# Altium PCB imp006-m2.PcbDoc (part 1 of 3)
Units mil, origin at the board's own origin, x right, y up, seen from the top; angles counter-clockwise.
Board outline 1181.1 x 1515.75 mil, 4 copper layers (Top Layer, Signal Layer 1, Signal Layer 2, Bottom Layer), stack 31.759 mil thick; 78 components, 116 nets, 508 pads, 482 vias.
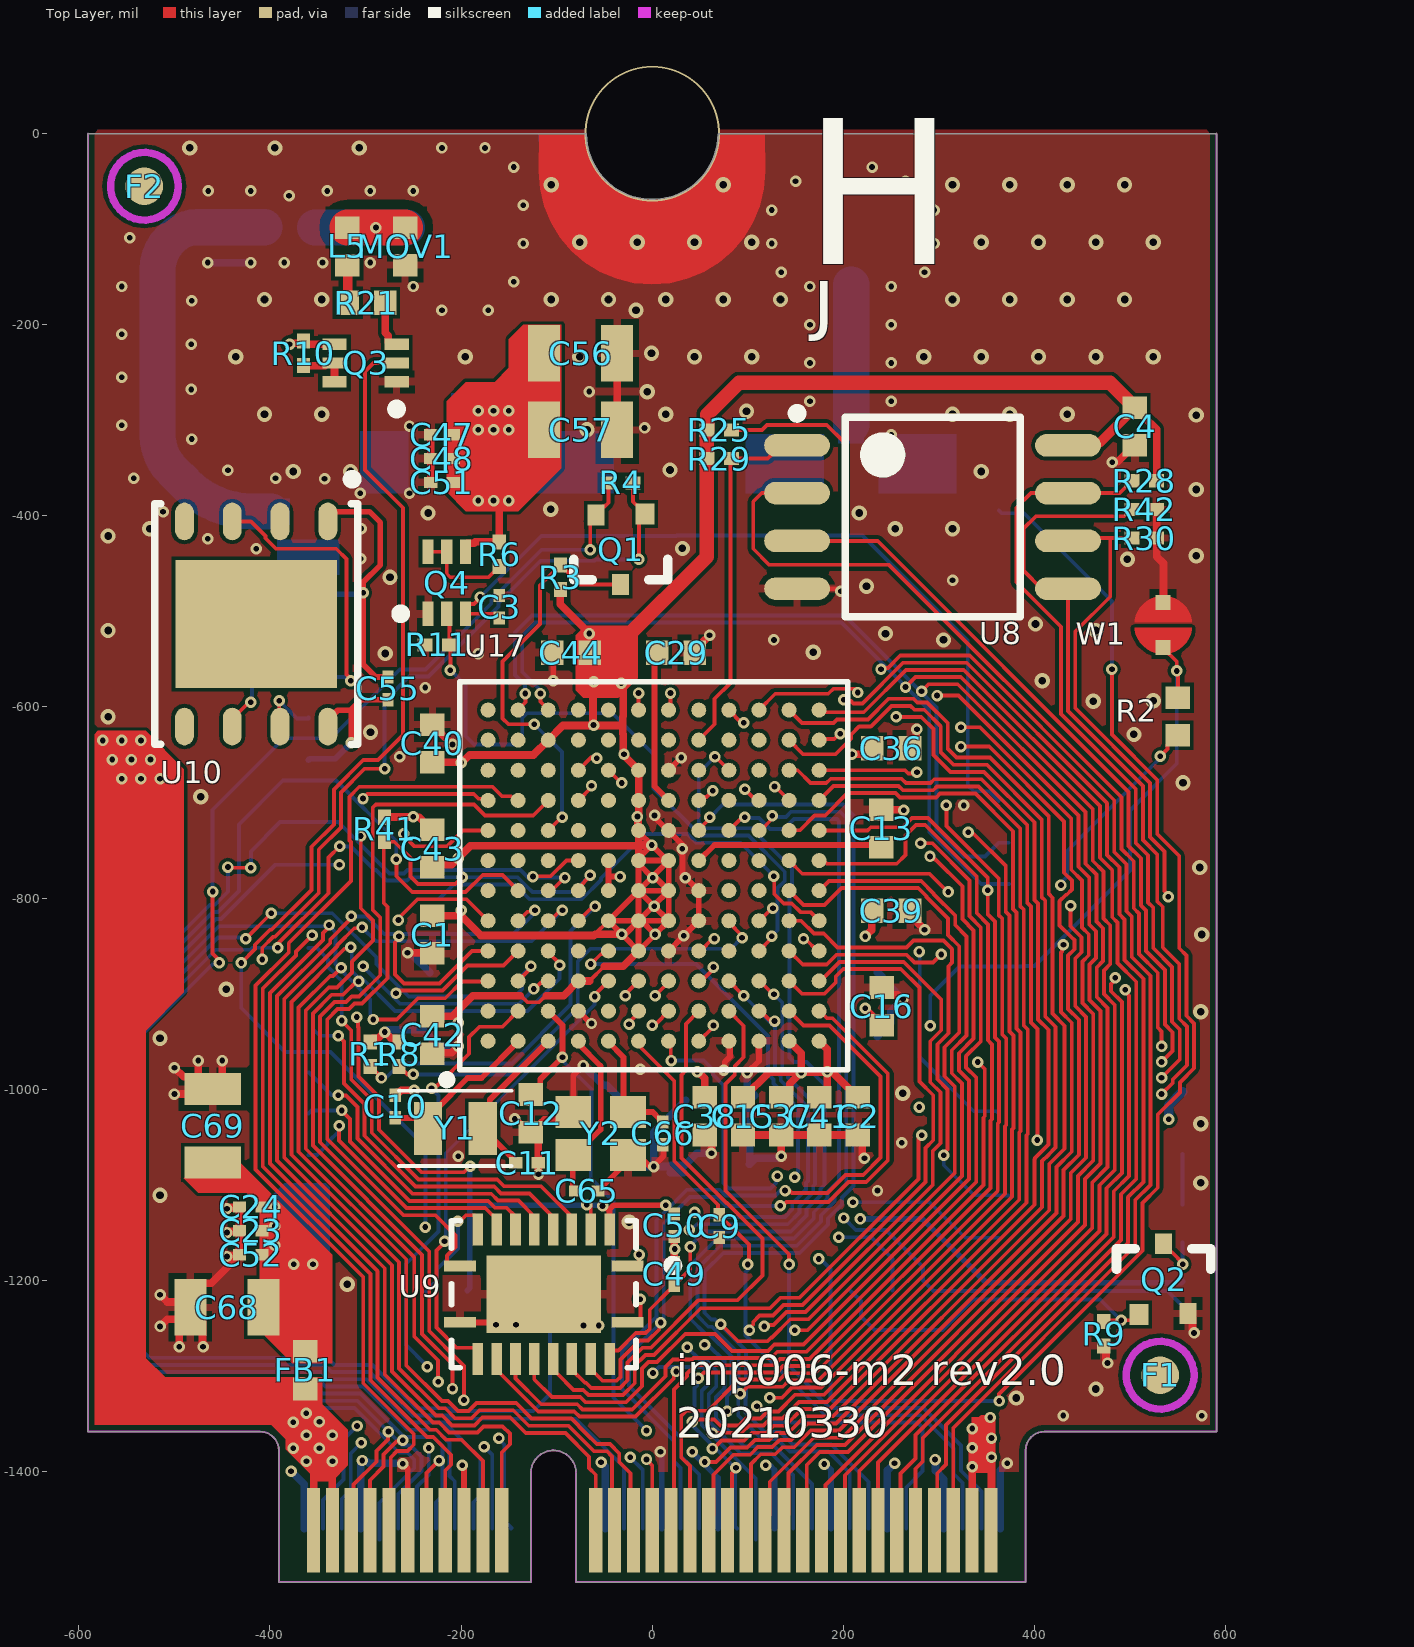
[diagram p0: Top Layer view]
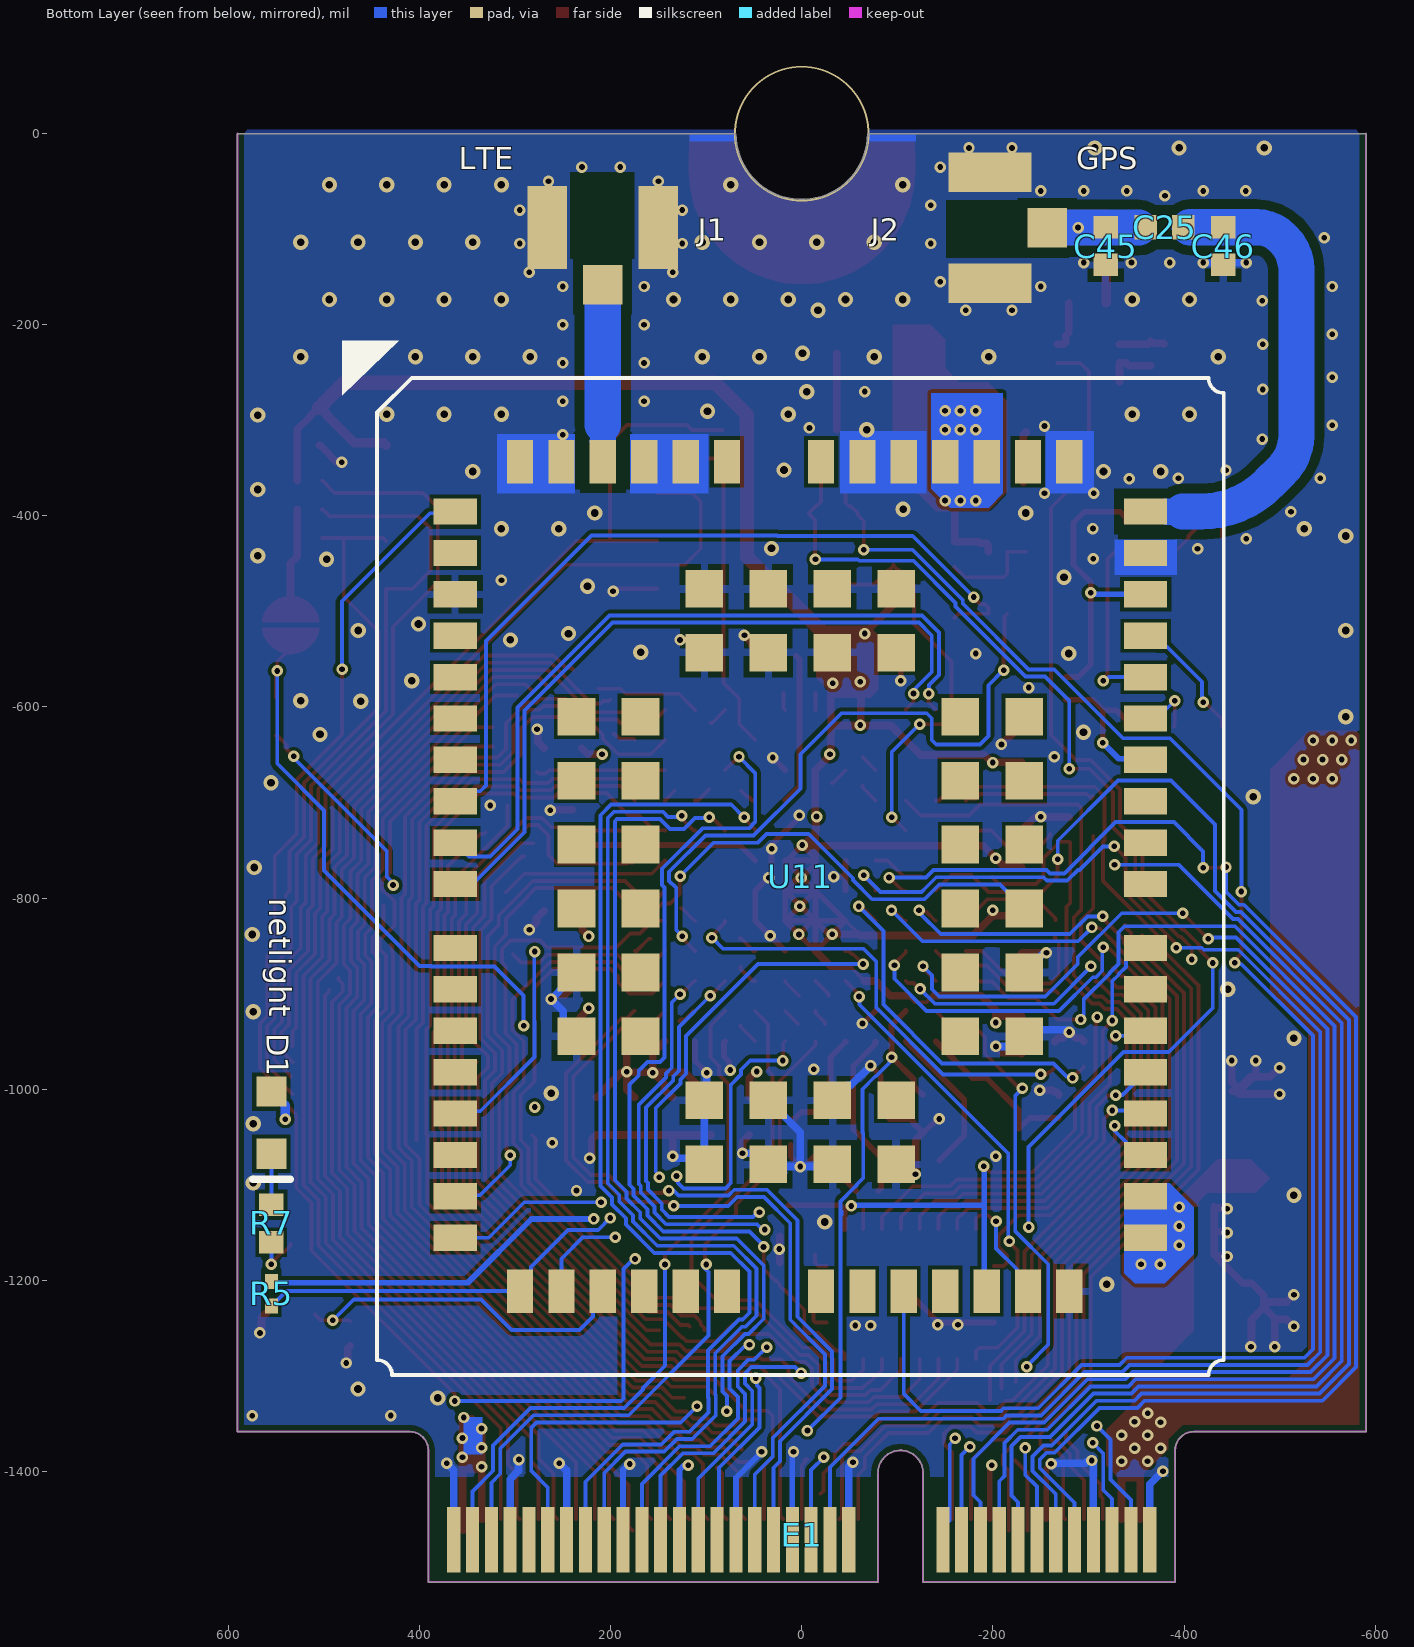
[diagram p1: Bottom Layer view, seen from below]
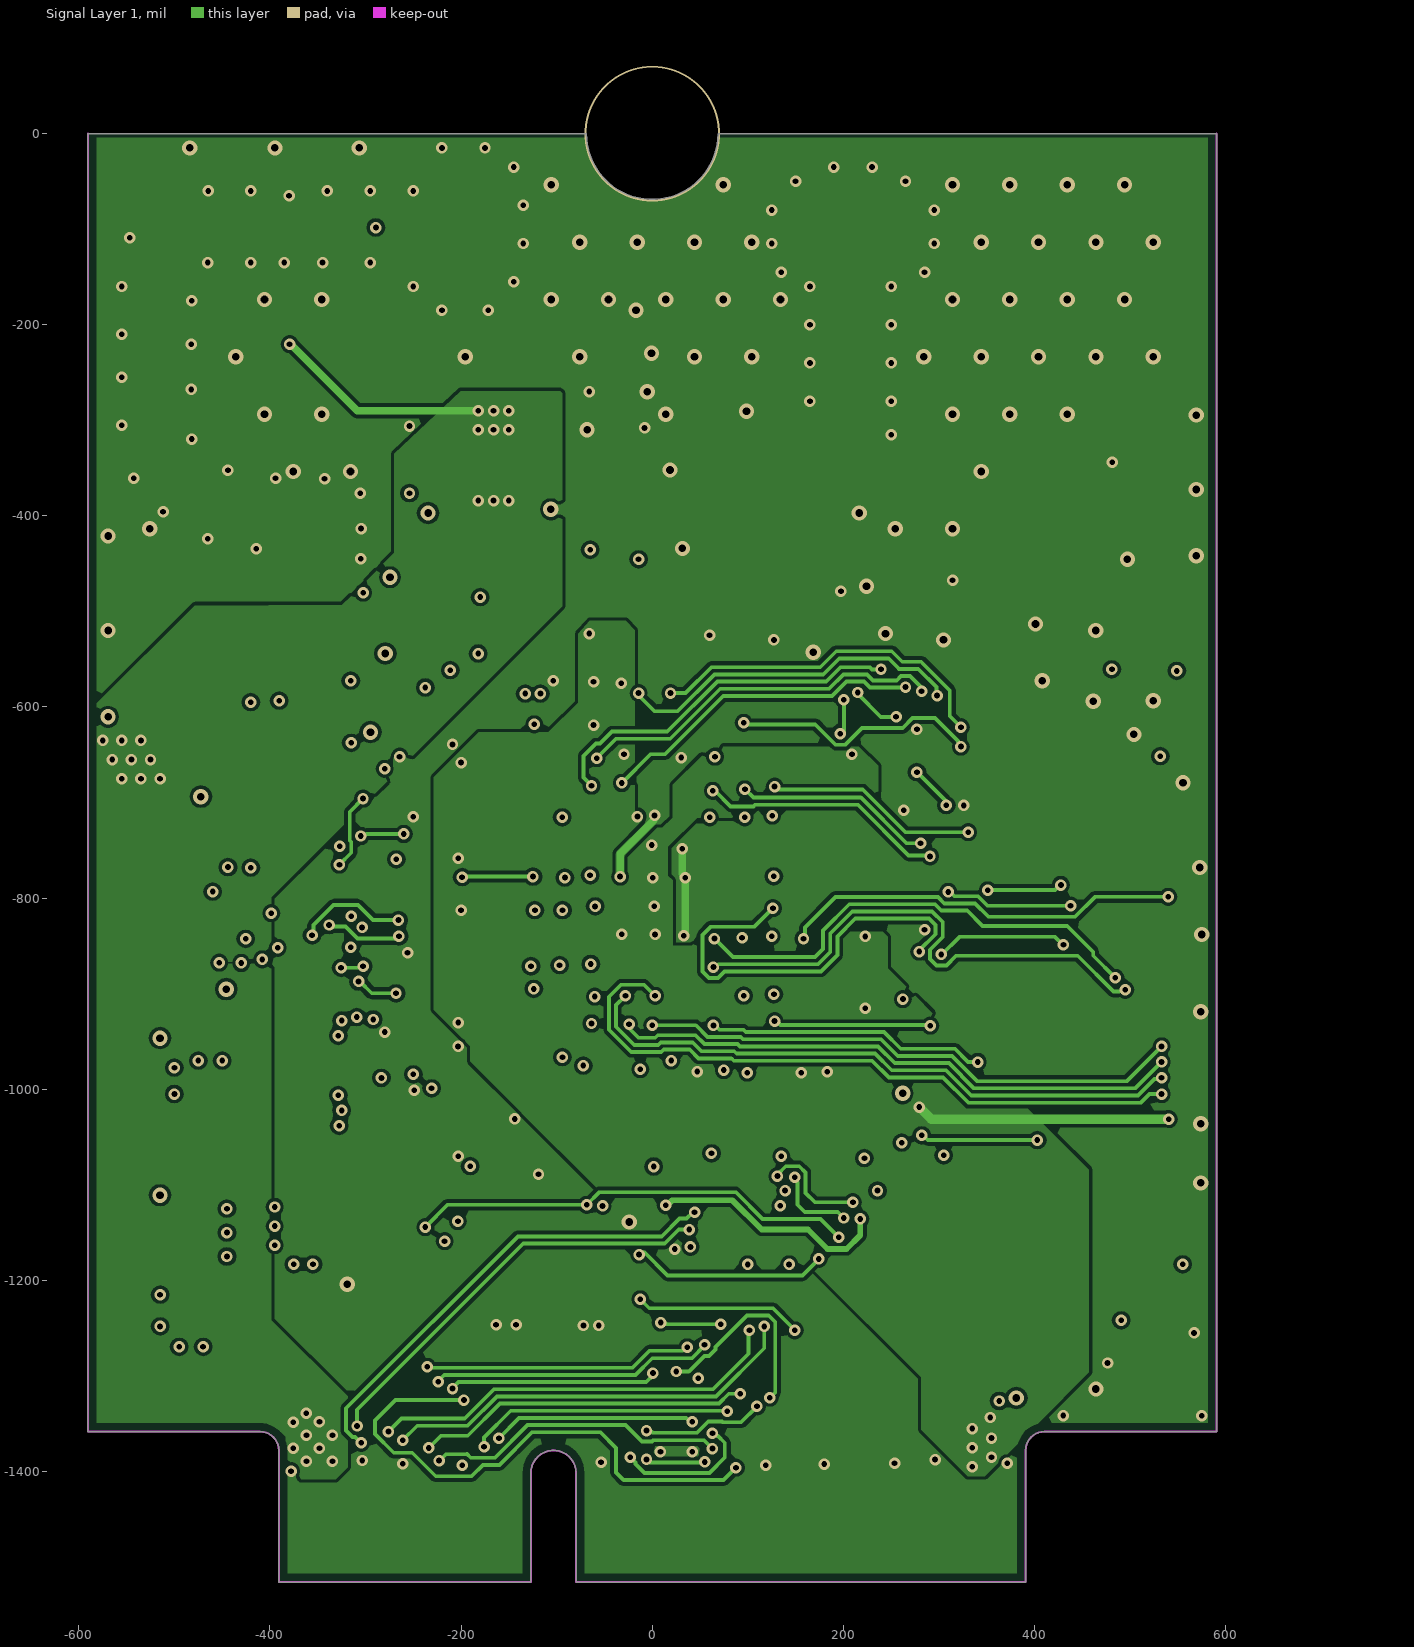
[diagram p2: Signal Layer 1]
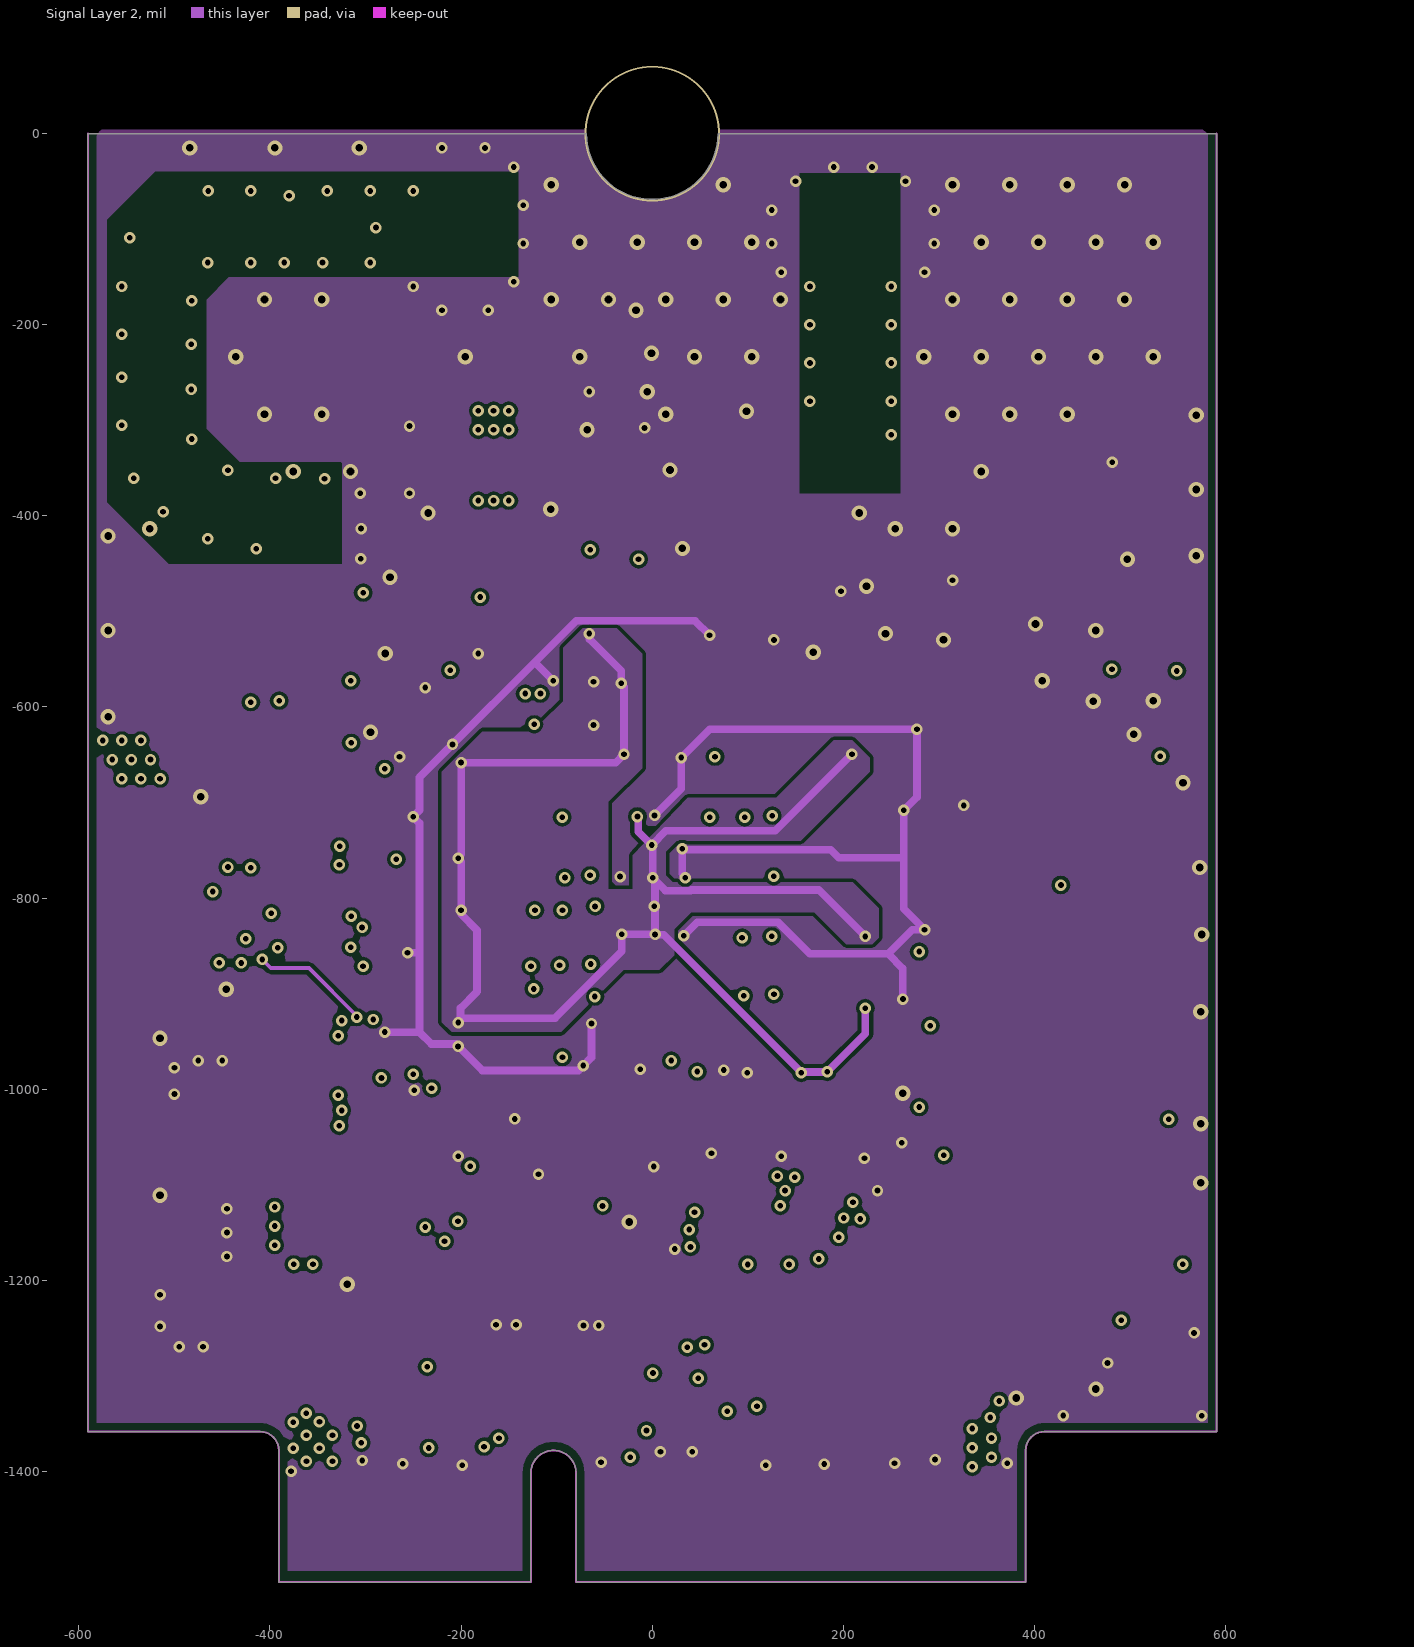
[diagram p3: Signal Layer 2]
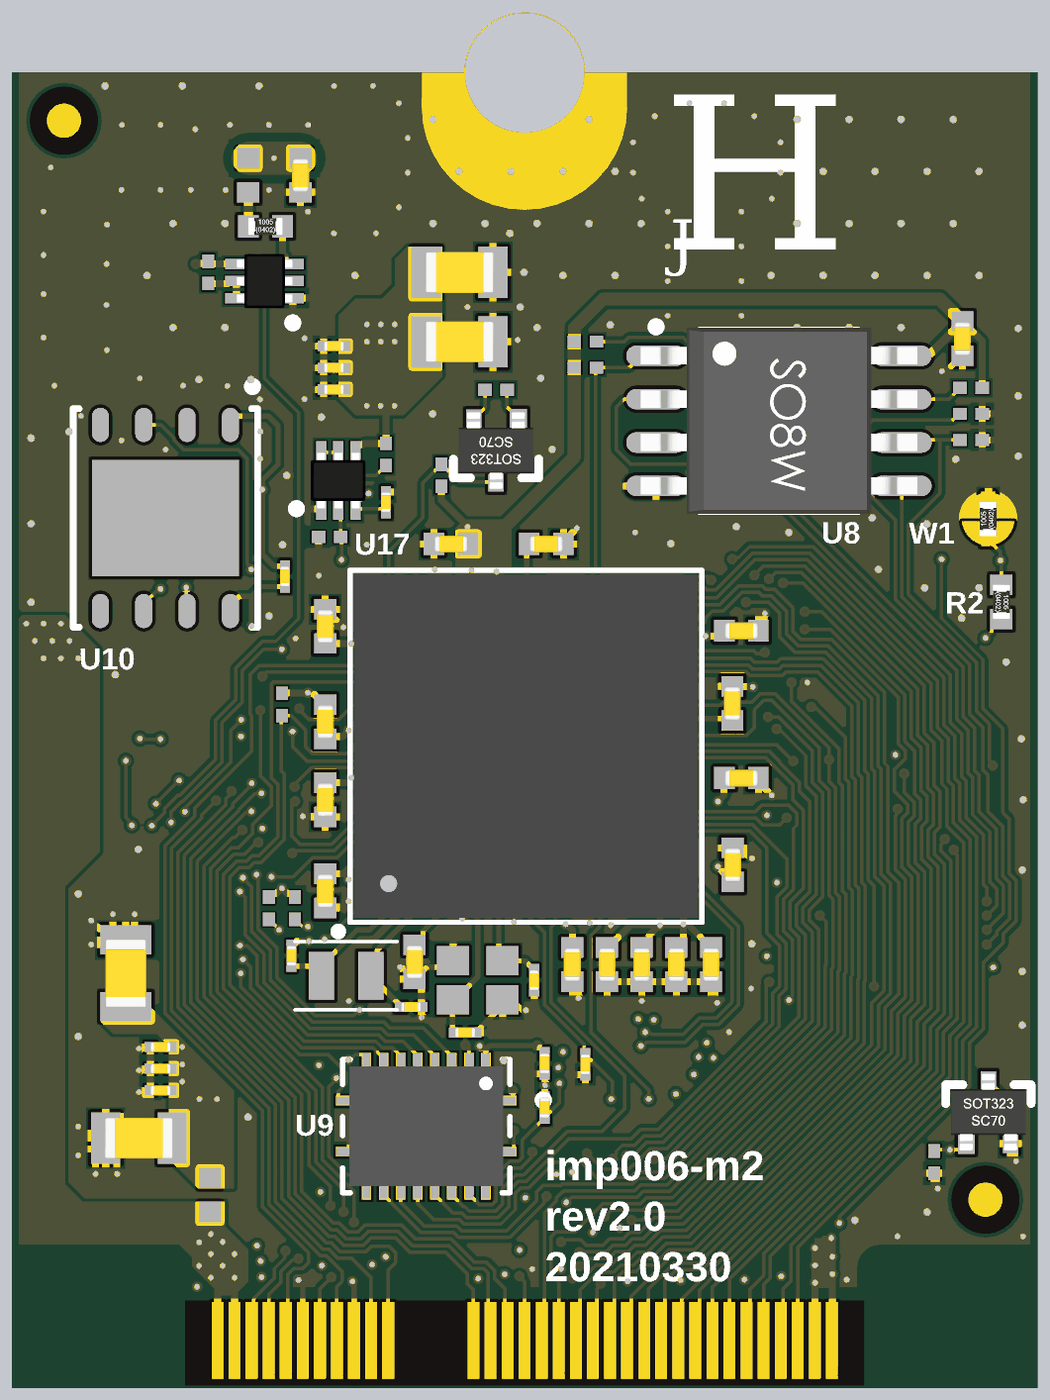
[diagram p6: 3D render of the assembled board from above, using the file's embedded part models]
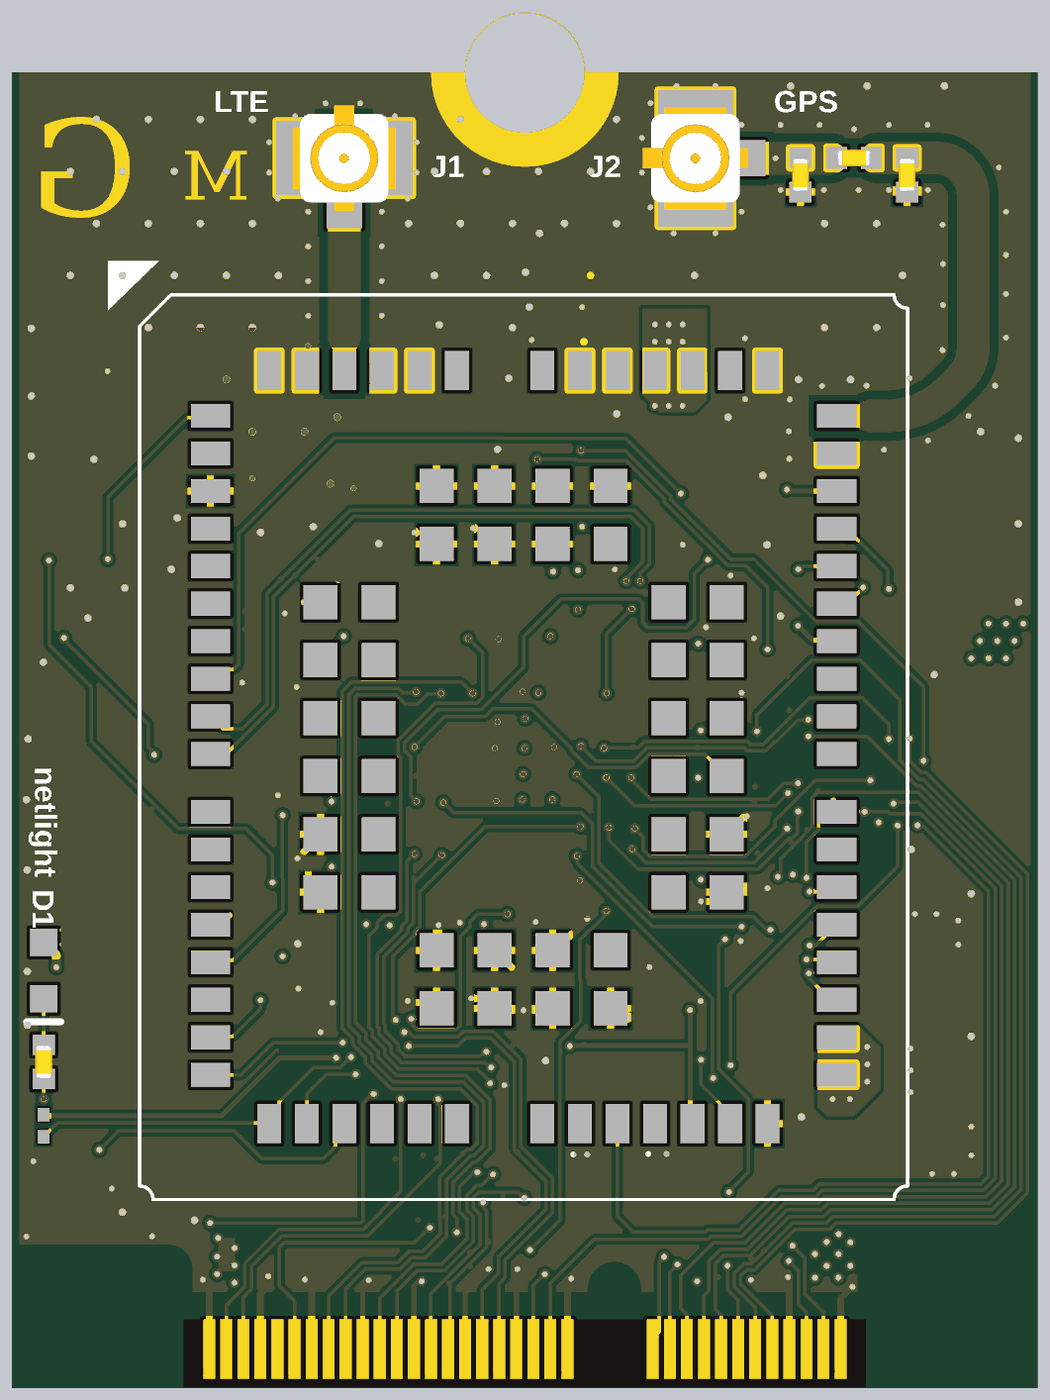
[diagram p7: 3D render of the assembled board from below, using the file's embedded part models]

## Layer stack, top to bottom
Top Solder: solder mask 0.4, Solder Resist, Dk 3.5
Top Layer: signal copper 1.4
Dielectric 1: prepreg 2.7559, FR-4, Dk 3.86
Signal Layer 1: signal copper 0.7
Dielectric 2: core 22.0469, FR-4, Dk 4.27
Signal Layer 2: signal copper 0.7
Dielectric 3: prepreg 2.7559, FR-4, Dk 3.86
Bottom Layer: signal copper 1.4
Bottom Solder: solder mask 0.4, Solder Resist, Dk 3.5

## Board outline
-390.75,-1515.75 -126.97,-1515.75 -126.97,-1401.6 cw(c-103.35,-1401.57) -79.72,-1401.6 -79.72,-1515.75 390.75,-1515.75 390.75,-1377.95 cw(c410.43,-1377.95) 410.43,-1358.27 590.55,-1358.27 590.55,0 68.9,0 cw(c0,0) -68.9,0 -590.55,0 -590.55,-1358.27 -410.43,-1358.27 cw(c-410.43,-1377.95) -390.75,-1377.95

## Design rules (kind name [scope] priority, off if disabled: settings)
Clearance Clearance_50OhmLTE [InNetClass('50_Ohm_LTE')] p1: gap=3.5 ignorepadtopadclearanceinfootprint=FALSE except(0: Arc-Hole Track-Hole SMDPad-Hole THPad-Hole Via-Hole Fill-Hole Poly-Hole Region-Hole Text-Hole; 10: Arc-Fill Arc-Poly Arc-Region Track-Fill Track-Poly Track-Region SMDPad-Fill SMDPad-Poly SMDPad-Region)
Clearance Clearance_Text [IsTextInverted] p2: gap=0 ignorepadtopadclearanceinfootprint=FALSE
Clearance Clearance_RF [InNetClass('50_Ohm') and (IsTrack or IsArc) vs InPolygon] p3: gap=30 ignorepadtopadclearanceinfootprint=FALSE except(0: Arc-Hole Track-Hole SMDPad-Hole THPad-Hole Via-Hole Fill-Hole Poly-Hole Region-Hole Text-Hole)
Clearance Clearance_USB [InNetClass('USB') and (IsTrack or IsArc) vs InPolygon] p4: gap=10 ignorepadtopadclearanceinfootprint=FALSE except(0: Arc-Hole Track-Hole SMDPad-Hole THPad-Hole Via-Hole Fill-Hole Poly-Hole Region-Hole Text-Hole)
Clearance Clearance_OuterPlane [OnLayer('Keep-Out Layer') vs (InPolygon and (OnLayer('Top Layer') or   OnLayer('Bottom Layer')))] p5: gap=6 ignorepadtopadclearanceinfootprint=FALSE except(0: Arc-Hole Track-Hole SMDPad-Hole THPad-Hole Via-Hole Fill-Hole Poly-Hole Region-Hole Text-Hole)
Clearance Clearance_InnerPlane [OnLayer('Keep-Out Layer') vs (InPolygon and (OnLayer('Signal Layer 1') or    OnLayer('Signal Layer 2')))] p6: gap=4 ignorepadtopadclearanceinfootprint=FALSE except(0: Arc-Hole Track-Hole SMDPad-Hole THPad-Hole Via-Hole Fill-Hole Poly-Hole Region-Hole Text-Hole; 8: Arc-Poly Track-Poly)
Clearance [All] p7: gap=3.5 ignorepadtopadclearanceinfootprint=FALSE except(0: Arc-Hole Track-Hole SMDPad-Hole THPad-Hole Via-Hole Fill-Hole Poly-Hole Region-Hole Text-Hole; 4: Arc-Fill Arc-Poly Arc-Region Track-Fill Track-Poly Track-Region SMDPad-Fill SMDPad-Poly SMDPad-Region)
ComponentClearance [All] p1: gap=2 collisioncheckmode=3 verticalgap=2 showdistances=FALSE
HoleSize [All] p1: absolutevalues=TRUE maxlimit=141.73 minlimit=1 maxpercent=80.000 minpercent=20.000
MinimumSolderMaskSliver [All] p1: minsoldermaskwidth=1.5
PolygonConnect PolygonConnect_GND_uFl [InNet('GND') vs InComponent('J1') or InComponent('J2') or InComponent('J3')] p1: connectstyle=Direct reliefconductorwidth=8 reliefentries=4 polygonreliefangle="90 Angle" airgapwidth=8
PolygonConnect PolygonConnect_VDD_Via [InNet('VDD') vs IsVia or IsPad] p2: connectstyle=Direct reliefconductorwidth=8 reliefentries=4 polygonreliefangle="90 Angle" airgapwidth=8
PolygonConnect PolygonConnect_VMOD_Via [InNet('VMOD') vs IsVia] p3: connectstyle=Direct reliefconductorwidth=8 reliefentries=4 polygonreliefangle="90 Angle" airgapwidth=8
PolygonConnect PolygonConnect_VBUS_Via [InNet('VBUS') vs IsVia or IsPad] p4: connectstyle=Direct reliefconductorwidth=8 reliefentries=4 polygonreliefangle="90 Angle" airgapwidth=8
PolygonConnect PolygonConnect_VBATT_Via [InNet('VBATT') vs IsVia or IsPad] p5: connectstyle=Direct reliefconductorwidth=8 reliefentries=4 polygonreliefangle="90 Angle" airgapwidth=8
PolygonConnect PolygonConnect_GND_Via [InNet('GND') vs IsVia] p6: connectstyle=Direct reliefconductorwidth=8 reliefentries=4 polygonreliefangle="90 Angle" airgapwidth=8
PolygonConnect [All] p7: connectstyle=Relief reliefconductorwidth=8 reliefentries=4 polygonreliefangle="90 Angle" airgapwidth=6
RoomDefinition imp006-m2-EdgeConnector [InComponentClass('imp006-m2-EdgeConnector')] p1 off: confinementstyle=ConfineIn formatcopy=TRUE lockcomponents=FALSE outline -3765.75,-4073.62 -1765.75,-4073.62 -1765.75,-3073.62 -3765.75,-3073.62
RoomDefinition imp006-m2-BG96 [InComponentClass('imp006-m2-BG96')] p2 off: confinementstyle=ConfineIn formatcopy=TRUE lockcomponents=FALSE outline -3765.75,-4073.62 -1765.75,-4073.62 -1765.75,-3073.62 -3765.75,-3073.62
RoomDefinition imp006-m2-MCU [InComponentClass('imp006-m2-MCU')] p3 off: confinementstyle=ConfineIn formatcopy=TRUE lockcomponents=FALSE outline 1281.46,-126.46 1084.46,-126.46 1084.46,-314.46 1281.46,-314.46
RoutingVias [All] p1: holewidth=8 width=12 viastyle="Through Hole" minholewidth=6 minwidth=12 maxholewidth=28 maxwidth=50
ShortCircuit ShortCircuitText [IsTextInverted] p1: allowed=TRUE
ShortCircuit [All] p2: allowed=FALSE
SilkToSilkClearance [All] p1: silktosilkclearance=0
SilkToSolderMaskClearance [IsPad] p1: minsilkscreentomaskgap=0 clearancetoexposedcopper=TRUE
SolderMaskExpansion [All] p1: expansion=4 istentingtop=FALSE
Width Width_50OhmLTE [InNetClass('50_Ohm_LTE')] p1: maxlimit=37.83 minlimit=37.76 preferedwidth=37.8
Width [All] p2: maxlimit=60 minlimit=4 preferedwidth=4 toplayer_maxwidth=50 midlayer1_maxwidth=50 bottomlayer_maxwidth=50 minimp=50.000000 maximp=50.000000 favimp=50.000000
24 further rules are at their usual default settings.

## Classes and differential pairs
net class 50_Ohm_LTE: RF_1_ANT RF_2 RF_2_ANT
component class imp006-m2-MCU: C1 C2 C4 C9 C10 C11 C12 C13 C15 C16 C29 C36 C37 C38 C39 C40 C41 C42 C43 C44 C65 C66 L1 R1 R2 R8 R25 R28 R29 R30 R42 U8 U17 W1 Y1 Y2
component class imp006-m2-BG96: C3 C23 C24 C25 C35 C45 C46 C47 C48 C49 C50 C51 C52 C55 C56 C57 C68 C69 D1 FB1 J1 J2 L5 MOV1 Q1 Q2 Q3 Q4 R3 R4 R5 R6 R7 R9 R10 R11 R21 R41 U9 U10 U11
component class imp006-m2-EdgeConnector: E1 F1 F2

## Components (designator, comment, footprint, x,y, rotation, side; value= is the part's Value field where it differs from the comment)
C1 "Ceramic Capacitor" CAPC1005X07M -230,-838.19 r90 top value=0.1uF
C2 "Ceramic Capacitor" CAPC1005X07M 215,-1028.19 r90 top value=1.0uF
C3 "Ceramic Capacitor" CAPC0603X03N -160,-495 r270 top value=0.1uF
C4 "Ceramic Capacitor" CAPC1005X07M 505,-306.46 r90 top value=1.0uF
C9 "Ceramic Capacitor" CAPC0603X03N 70,-1143.19 r90 top value=0.1uF
C10 "Ceramic Capacitor" CAPC0603X03N -269,-1018 r270 top value=8pF
C11 "Ceramic Capacitor" CAPC0603X03N -131,-1077 r180 top value=8pF
C12 "Ceramic Capacitor" CAPC1005X07M -127,-1025.19 r90 top value=1.0uF
C13 "Ceramic Capacitor" CAPC1005X07M 239.57,-727.06 r270 top value=2.2uF
C15 "Ceramic Capacitor" CAPC1005X07M 95,-1028.19 r90 top value=1.0uF
C16 "Ceramic Capacitor" CAPC1005X07M 240,-913.19 r270 top value=0.1uF
C23 "Ceramic Capacitor" CAPC0603X03N -420,-1148.19 r0 top value=33pF
C24 "Ceramic Capacitor" CAPC0603X03N -420,-1123.19 r0 top value=10pF
C25 "Ceramic Capacitor" CAPC1005X07M -379.68,-98 r180 bottom value=100pF
C29 "Ceramic Capacitor" CAPC1005X07M 25,-543.19 r180 top value=2.2uF
C36 "Ceramic Capacitor" CAPC1005X07M 250,-643.19 r180 top value=0.1uF
C37 "Ceramic Capacitor" CAPC1005X07M 135,-1028.19 r90 top value=0.1uF
C38 "Ceramic Capacitor" CAPC1005X07M 55,-1028.19 r90 top value=0.1uF
C39 "Ceramic Capacitor" CAPC1005X07M 250,-813.19 r180 top value=0.1uF
C40 "Ceramic Capacitor" CAPC1005X07M -230,-638.19 r270 top value=0.1uF
C41 "Ceramic Capacitor" CAPC1005X07M 175,-1028.19 r90 top value=0.1uF
C42 "Ceramic Capacitor" CAPC1005X07M -230,-943.19 r90 top value=0.1uF
C43 "Ceramic Capacitor" CAPC1005X07M -230,-748.19 r270 top value=0.1uF
C44 "Ceramic Capacitor" CAPC1005X07M -85,-543.19 r0 top value=4.7uF
C45 "Ceramic Capacitor" CAPC1005X07M -318,-117.68 r90 bottom value=100pF
C46 "Ceramic Capacitor" CAPC1005X07M -441,-117.68 r90 bottom value=100pF
C47 "Ceramic Capacitor" CAPC0603X03N -220,-315 r0 top value=0.1uF
C48 "Ceramic Capacitor" CAPC0603X03N -220,-340 r0 top value=33pF
C49 "Ceramic Capacitor" CAPC0603X03N 23,-1193.19 r270 top value=0.1uF
C50 "Ceramic Capacitor" CAPC0603X03N 23,-1142.19 r90 top value=0.1uF
C51 "Ceramic Capacitor" CAPC0603X03N -220,-365 r0 top value=10pF
C52 "Ceramic Capacitor" CAPC0603X03N -420,-1173.19 r0 top value=0.1uF
C55 "Ceramic Capacitor" CAPC0603X03N -276.5,-580.54 r270 top value=0.1uF
C56 "Ceramic Capacitor" CAPC2012X14N -75,-230 r180 top value=47uF
C57 "Ceramic Capacitor" CAPC2012X14N -75,-310 r180 top value=47uF
C65 "Ceramic Capacitor" CAPC0603X03N -68.54,-1106.46 r180 top value=12pF
C66 "Ceramic Capacitor" CAPC0603X03N 11,-1046.19 r90 top value=12pF
C68 "Ceramic Capacitor" CAPC2012X14N -445,-1228.19 r0 top value=47uF
C69 "Ceramic Capacitor" CAPC2012X14N -460,-1038.19 r270 top value=47uF
D1 "LED Green" LED1608X08N-GRN 555,-1035 r90 bottom
E1 "imp006 Edge Connector" NGFF_EDGE75_E 390.75,-1515.75 r180 bottom
F1 "Fiducial" FIDUCIAL1MM 531.5,-1299.21 r0 top net-tie
F2 "Fiducial" FIDUCIAL1MM -531.5,-55.12 r180 top net-tie
FB1 "Ferrite Bead" INDC1005X06M -363,-1294 r90 top
J1 "U.FL RCPT" RF_RCPT_UFL_400X400 208.31,-98.32 r180 bottom
J2 "U.FL RCPT" RF_RCPT_UFL_400X400 -196.85,-98.43 r90 bottom
L5 "INDUCTOR" INDC1005X06M -319,-118 r90 top value=27nH
MOV1 "MOV" CAPC1005X07M -258.56,-118 r90 top
Q1 "N-Channel MOSFET" SOT65P200X125-3N -33.03,-435.46 r270 top
Q2 "N-Channel MOSFET" SOT65P200X125-3N 535,-1198.19 r90 top
Q3 "DMC2400UV-7" SOTFL50P162X66-6N -300,-240 r180 top
Q4 "N-FET + P-FET" SOTFL50P162X66-6N -215,-470 r90 top
R1 "Resistor" RESC0603X03M -295,-963.19 r90 top value=10K
R2 "Resistor" RESC1005X04M 550,-610 r270 top value=0.0
R3 "Resistor" RESC0603X03M -96.1,-464.05 r90 top value=10K
R4 "Resistor" RESC0603X03M -33.05,-365.46 r180 top value=10K
R5 "Resistor" RESC0603X03M 555,-1214 r270 bottom value=100K
R6 "Resistor" RESC0603X03M -160,-440 r270 top value=100K
R7 "Resistor" CAPC1005X07M 555,-1140.47 r270 bottom value=220
R8 "Resistor" RESC0603X03M -265,-963.19 r90 top value=10K
R9 "Resistor" RESC0603X03M 472.44,-1255.91 r270 top value=100K
R10 "Resistor" RESC0603X03M -365,-230 r270 top value=100K
R11 "Resistor" RESC0603X03M -225,-535 r180 top value=100K
R21 "Resistor" RESC1005X04M -299,-177 r0 top value=10
R25 "Resistor" RESC0603X03M 70,-310 r0 top value=100K
R28 "Resistor" RESC0603X03M 515,-363.19 r180 top value=100K
R29 "Resistor" RESC0603X03M 70,-340 r0 top value=100K
R30 "Resistor" RESC0603X03M 515,-423.19 r0 top value=1M
R41 "Resistor" RESC0603X03M -280,-728.19 r270 top value=1M
R42 "Resistor" RESC0603X03M 515,-393.19 r0 top value=100K
U8 "MX25R6435FZAIH0" SOP127P790X216-8N 293.31,-401.22 r0 top
U9 "TXS0108ERGYR" QFN50P450X350X100_HS-21N -113.54,-1214.46 r270 top value=Value
U10 "eSIM" QFN127P600X500X80_HS-9N -414.43,-513.17 r270 top
U11 "BG96" BG96_20170711 1.45,-777.4 r180 bottom locked
U17 "imp006" STM-UFBGA144 1.46,-776.46 r90 top locked value=Value
W1 "Shortpads" SHORTBRIDGE 534.67,-514.29 r90 top
Y1 "XTAL" XTAL_20X12X06-2N -206,-1041 r0 top
Y2 "XTAL_20X16_26MHZ" XTAL_20X16X07-4N -54,-1046.19 r0 top

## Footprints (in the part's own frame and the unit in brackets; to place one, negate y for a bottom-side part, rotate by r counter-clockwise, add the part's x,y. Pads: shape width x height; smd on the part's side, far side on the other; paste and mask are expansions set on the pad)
BG96_20170711 [mm]
  rect 1.15x0.7 smd: 1(-9.175,9.7) 2(-9.175,8.6) 3(-9.175,7.5) 4(-9.175,6.4) 5(-9.175,5.3) 6(-9.175,4.2) 7(-9.175,3.1) 8(-9.175,2) 9(-9.175,0.9) 10(-9.175,-0.2) 11(-9.175,-1.9) 12(-9.175,-3) 13(-9.175,-4.1) 14(-9.175,-5.2) 15(-9.175,-6.3) 16(-9.175,-7.4) 17(-9.175,-8.5) 18(-9.175,-9.6) 32(9.175,-9.6) 33(9.175,-8.5) 34(9.175,-7.4) 35(9.175,-6.3) 36(9.175,-5.2) 37(9.175,-4.1) 38(9.175,-3) 39(9.175,-1.9) 40(9.175,-0.2) 41(9.175,0.9) 42(9.175,2) 43(9.175,3.1) 44(9.175,4.2) 45(9.175,5.3) 46(9.175,6.4) 47(9.175,7.5) 48(9.175,8.6) 49(9.175,9.7)
  rect 0.7x1.15 smd: 19(-7.45,-11.025) 20(-6.35,-11.025) 21(-5.25,-11.025) 22(-4.15,-11.025) 23(-3.05,-11.025) 24(-1.95,-11.025) 25(0.55,-11.025) 26(1.65,-11.025) 27(2.75,-11.025) 28(3.85,-11.025) 29(4.95,-11.025) 30(6.05,-11.025) 31(7.15,-11.025) 50(7.15,11.025) 51(6.05,11.025) 52(4.95,11.025) 53(3.85,11.025) 54(2.75,11.025) 55(1.65,11.025) 56(0.55,11.025) 57(-1.95,11.025) 58(-3.05,11.025) 59(-4.15,11.025) 60(-5.25,11.025) 61(-6.35,11.025) 62(-7.45,11.025)
  rect 1x1 smd: 63(-5.95,4.25) 64(-5.95,2.55) 65(-5.95,0.85) 66(-5.95,-0.85) 67(-5.95,-2.55) 68(-5.95,-4.25) 69(-2.55,-7.65) 70(-0.85,-7.65) 71(0.85,-7.65) 72(2.55,-7.65) 73(5.95,-4.25) 74(5.95,-2.55) 75(5.95,-0.85) 76(5.95,0.85) 77(5.95,2.55) 78(5.95,4.25) 79(2.55,7.65) 80(0.85,7.65) 81(-0.85,7.65) 82(-2.55,7.65) 83(-4.25,4.25) 84(-4.25,2.55) 85(-4.25,0.85) 86(-4.25,-0.85) 87(-4.25,-2.55) 88(-4.25,-4.25) 89(-2.55,-5.95) 90(-0.85,-5.95) 91(0.85,-5.95) 92(2.55,-5.95) 93(4.25,-4.25) 94(4.25,-2.55) 95(4.25,-0.85) 96(4.25,0.85) 97(4.25,2.55) 98(4.25,4.25) 99(2.55,5.95) 100(0.85,5.95) 101(-0.85,5.95) 102(-2.55,5.95)
  silkscreen extent -12.18,-13.25 11.25,14.24, body extent -11.4,-13.4 11.4,13.4, height 2.3
CAPC0603X03N [mm] "Chip Capacitor, 2-Leads, Body 0.6x0.3mm, IPC Medium Density"
  rect 0.35x0.3 smd mask+0.075: 1(-0.3,0) 2(0.3,0)
  body extent -0.3,-0.15 0.3,0.15, height 0.33
CAPC1005X07M [mm] "Chip Capacitor, 2-Leads, Body 1.0x0.5mm, IPC Medium Density"
  rect 0.6x0.65 smd: 1(-0.5,0) 2(0.5,0)
  body extent -0.5,-0.25 0.5,0.25, height 0.55
CAPC2012X14N [mm] "Chip Capacitor, 2-Leads, Body 2.0x1.3mm, IPC Medium Density"
  rect 0.85x1.5 smd: 1(-0.975,0) 2(0.975,0)
  body extent -1,-0.6 1,0.6, height 1.4
FIDUCIAL1MM [mm] "FIDUCIAL, 1MM Diameter"
  round 1 smd paste-1 mask+0.5: 0(0,0)
  Top Layer keep-out circle w0.2: c0,0 r0.9
INDC1005X06M [mm] "Chip Inductor, 2-Leads, Body 1.0x0.5mm, IPC Medium Density"
  rect 0.6x0.65 smd: 1(-0.5,0) 2(0.5,0)
  body extent -0.53,-0.28 0.53,0.27, height 0.55
LED1608X08N-GRN [mm] "LED, 0603 (1608 metric), Green"
  rect 0.8x0.8 smd: A(0.825,0) K(-0.825,0)
  silkscreen extent -1.5,-0.5 -1.5,0.5, body extent -0.8,-0.4 0.8,0.4, height 0.8
NGFF_EDGE75_E [mm] "Edge Connector, M2.COM NGFF Key E"
  rect 0.35x1.75 smd paste-0.9: 1(19.175,1.125) 1(19.175,1.125) 3(18.675,1.125) 5(18.175,1.125) 7(17.675,1.125) 9(17.175,1.125) 11(16.675,1.125) 13(16.175,1.125) 15(15.675,1.125) 17(15.175,1.125) 19(14.675,1.125) 21(14.175,1.125) 23(13.675,1.125) 33(11.175,1.125) 35(10.675,1.125) 37(10.175,1.125) 39(9.675,1.125) 41(9.175,1.125) 43(8.675,1.125) 45(8.175,1.125) 47(7.675,1.125) 49(7.175,1.125) 51(6.675,1.125) 53(6.175,1.125) 55(5.675,1.125) 57(5.175,1.125) 59(4.675,1.125) 61(4.175,1.125) 63(3.675,1.125) 65(3.175,1.125) 67(2.675,1.125) 69(2.175,1.125) 71(1.675,1.125) 73(1.175,1.125) 75(0.675,1.125)
  rect 0.35x2.25 smd far side paste-0.9: 2(18.925,1.375) 4(18.425,1.375) 6(17.925,1.375) 8(17.425,1.375) 10(16.925,1.375) 12(16.425,1.375) 14(15.925,1.375) 16(15.425,1.375) 18(14.925,1.375) 20(14.425,1.375) 22(13.925,1.375) 32(11.425,1.375) 34(10.925,1.375) 36(10.425,1.375) 38(9.925,1.375) 40(9.425,1.375) 42(8.925,1.375) 44(8.425,1.375) 46(7.925,1.375) 48(7.425,1.375) 50(6.925,1.375) 52(6.425,1.375) 54(5.925,1.375) 56(5.425,1.375) 58(4.925,1.375) 60(4.425,1.375) 62(3.925,1.375) 64(3.425,1.375) 66(2.925,1.375) 68(2.425,1.375) 70(1.925,1.375) 72(1.425,1.375) 74(0.925,1.375)
QFN50P450X350X100_HS-21N [mm]
  rect 0.28x0.85 smd paste-0.412 mask+0: 1(-0.75,2.225) 10(-0.75,-2.225) 11(0.75,-2.225) 20(0.75,2.225)
  rect 0.85x0.28 smd paste-0.412 mask+0: 2(-1.725,1.75) 3(-1.725,1.25) 4(-1.725,0.75) 5(-1.725,0.25) 6(-1.725,-0.25) 7(-1.725,-0.75) 8(-1.725,-1.25) 9(-1.725,-1.75) 12(1.725,-1.75) 13(1.725,-1.25) 14(1.725,-0.75) 15(1.725,-0.25) 16(1.725,0.25) 17(1.725,0.75) 18(1.725,1.25) 19(1.725,1.75)
  rect 2.05x3.05 smd paste-1.512 mask-1.511: 21(0,0)
  silkscreen extent -1.95,-2.45 1.95,3.56, body extent -1.75,-2.25 1.75,2.25, height 1
QFN127P600X500X80_HS-9N [mm] "QFN, 8-Leads, Body 6.00x5.00mm, Pitch 1.27mm, Thermal Pad 3.40x4.30mm, IPC Medium Density"
  oval 1x0.5 smd: 1(-2.725,1.905) 2(-2.725,0.635) 3(-2.725,-0.635) 4(-2.725,-1.905) 5(2.725,-1.905) 6(2.725,-0.635) 7(2.725,0.635) 8(2.725,1.905)
  rect 3.4x4.3 smd: 9(0,0)
  silkscreen extent -3.97,-2.7 3.2,2.7, body extent -3.05,-2.55 3.05,2.55, height 0.8
RESC0603X03M [mm]
  rect 0.4x0.35 smd mask+0.051: 1(-0.325,0) 2(0.325,0)
  body extent -0.31,-0.16 0.32,0.17, height 0.26
RESC1005X04M [mm] "Chip Resistor, 2-Leads, Body 1.0x0.5mm, IPC Medium Density"
  rect 0.6x0.65 smd: 1(-0.5,0) 2(0.5,0)
  body extent -0.5,-0.25 0.5,0.25, height 0.35
RF_RCPT_UFL_400X400 [mm]
  rect 1.05x2.2 smd: 1(-1.475,0) 3(1.475,0)
  rect 1.05x1.05 smd: 2(0,-1.525)
  body extent -1.5,-1.55 1.5,1.55, height 1.25
SHORTBRIDGE [mm]
  rect 0.4x0.4 smd paste-0.4: 1(-0.6,0) 2(0.6,0)
  Top Layer region: -0.127,-0.762 -0.457,-0.623 -0.689,-0.349 -0.773,0 -0.689,0.349 -0.457,0.623 -0.127,0.762 -0.127,0.762
  Top Layer region: 0.127,0.762 0.457,0.623 0.689,0.349 0.773,0 0.689,-0.349 0.457,-0.623 0.127,-0.762 0.127,-0.762
  Top Layer region: -0.127,0.762 -0.127,0.762 -0.076,0.762 -0.076,-0.762 -0.127,-0.762
  Top Layer region: 0.127,-0.762 0.127,-0.762 0.076,-0.762 0.076,0.762 0.127,0.762
  body extent -0.5,-0.25 0.5,0.25, height 0.35
SOP127P790X216-8N [mm] "SOP, 8-Leads, Body 5.23x5.28mm, Pitch 1.27mm, IPC Medium Density"
  oval 1.75x0.6 smd: 1(-3.6,1.905) 2(-3.6,0.635) 3(-3.6,-0.635) 4(-3.6,-1.905) 5(3.6,-1.905) 6(3.6,-0.635) 7(3.6,0.635) 8(3.6,1.905)
  silkscreen extent -3.72,-2.65 2.32,2.88, body extent -4.05,-2.73 4.05,2.73, height 1.75
SOT65P200X125-3N [mm] "SOT-323, SC-70"
  rect 0.55x0.5 smd: 1(-0.95,0.65)
  rect 0.55x0.45 smd: 2(-0.925,-0.65) 3(0.925,0)
  silkscreen extent 0.25,-1.25 0.8,1.25, body extent -1.12,-1.1 1.12,1.1, height 1.1
SOTFL50P162X66-6N [mm] "SOTFL, 6-Leads, Body 1.60x1.63mm, Pitch 0.50mm, IPC Medium Density"
  rect 0.65x0.3 smd mask+0.05: 1(-0.825,0.5) 2(-0.825,0) 3(-0.825,-0.5) 4(0.825,-0.5) 5(0.825,0) 6(0.825,0.5)
  silkscreen extent -0.95,1.1 -0.7,1.35, body extent -0.81,-0.8 0.81,0.8, height 0.58
STM-UFBGA144 [mm]
  round 0.4 smd: A1(-4.4,4.4) A2(-3.6,4.4) A3(-2.8,4.4) A4(-2,4.4) A5(-1.2,4.4) A6(-0.4,4.4) A7(0.4,4.4) A8(1.2,4.4) A9(2,4.4) A10(2.8,4.4) A11(3.6,4.4) A12(4.4,4.4) B1(-4.4,3.6) B2(-3.6,3.6) B3(-2.8,3.6) B4(-2,3.6) B5(-1.2,3.6) B6(-0.4,3.6) B7(0.4,3.6) B8(1.2,3.6) B9(2,3.6) B10(2.8,3.6) B11(3.6,3.6) B12(4.4,3.6) C1(-4.4,2.8) C2(-3.6,2.8) C3(-2.8,2.8) C4(-2,2.8) C5(-1.2,2.8) C6(-0.4,2.8) C7(0.4,2.8)
  round 0.4 smd paste+0 mask+0.075: C8(1.2,2.8) C9(2,2.8) C10(2.8,2.8) C11(3.6,2.8) C12(4.4,2.8) D1(-4.4,2) D2(-3.6,2) D3(-2.8,2) D4(-2,2) D5(-1.2,2) D6(-0.4,2) D7(0.4,2) D8(1.2,2) D9(2,2) D10(2.8,2) D11(3.6,2) D12(4.4,2) E1(-4.4,1.2) E2(-3.6,1.2) E3(-2.8,1.2) E4(-2,1.2) E5(-1.2,1.2) E6(-0.4,1.2) E7(0.4,1.2) E8(1.2,1.2) E9(2,1.2) E10(2.8,1.2) E11(3.6,1.2) E12(4.4,1.2) F1(-4.4,0.4) F2(-3.6,0.4) F3(-2.8,0.4) F4(-2,0.4) F5(-1.2,0.4) F6(-0.4,0.4) F7(0.4,0.4) F8(1.2,0.4) F9(2,0.4) F10(2.8,0.4) F11(3.6,0.4) F12(4.4,0.4) G1(-4.4,-0.4) G2(-3.6,-0.4) G3(-2.8,-0.4) G4(-2,-0.4) G5(-1.2,-0.4) G6(-0.4,-0.4) G7(0.4,-0.4) G8(1.2,-0.4) G9(2,-0.4) G10(2.8,-0.4) G11(3.6,-0.4) G12(4.4,-0.4) H1(-4.4,-1.2) H2(-3.6,-1.2) H3(-2.8,-1.2) H4(-2,-1.2) H5(-1.2,-1.2) H6(-0.4,-1.2) H7(0.4,-1.2) H8(1.2,-1.2) H9(2,-1.2) H10(2.8,-1.2) H11(3.6,-1.2) H12(4.4,-1.2) J1(-4.4,-2) J2(-3.6,-2) J3(-2.8,-2) J4(-2,-2) J5(-1.2,-2) J6(-0.4,-2) J7(0.4,-2) J8(1.2,-2) J9(2,-2) J10(2.8,-2) J11(3.6,-2) J12(4.4,-2) K1(-4.4,-2.8) K2(-3.6,-2.8) K3(-2.8,-2.8) K4(-2,-2.8) K5(-1.2,-2.8) K6(-0.4,-2.8) K7(0.4,-2.8) K8(1.2,-2.8) K9(2,-2.8) K10(2.8,-2.8) K11(3.6,-2.8) K12(4.4,-2.8) L1(-4.4,-3.6) L2(-3.6,-3.6) L3(-2.8,-3.6) L4(-2,-3.6) L5(-1.2,-3.6) L6(-0.4,-3.6) L7(0.4,-3.6) L8(1.2,-3.6) L9(2,-3.6) L10(2.8,-3.6) L11(3.6,-3.6) L12(4.4,-3.6) M1(-4.4,-4.4) M2(-3.6,-4.4) M3(-2.8,-4.4) M4(-2,-4.4) M5(-1.2,-4.4) M6(-0.4,-4.4) M7(0.4,-4.4) M8(1.2,-4.4) M9(2,-4.4) M10(2.8,-4.4) M11(3.6,-4.4) M12(4.4,-4.4)
  silkscreen extent -5.53,-5.16 5.16,5.6, body extent -5.03,-5.03 5.03,5.03, height 0.61
XTAL_20X12X06-2N [mm] "TUNING FORK CRYSTAL, 2PIN"
  rect 0.75x1.4 smd: 1(-0.725,0) 2(0.725,0)
  silkscreen extent -1.5,-1 1.5,1, body extent -1.1,-0.7 1.1,0.7, height 0.76
XTAL_20X16X07-4N [mm] "2.0X1.6 CRYSTAL, 0.7MM TALL"
  rect 0.95x0.85 smd mask+0.076: 1(-0.725,-0.575) 2(0.725,-0.575) 3(0.725,0.575) 4(-0.725,0.575)
  body extent -1,-0.8 1,0.8, height 0.55

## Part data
C1 C16 C36 C37 C38 C39 C40 C41 C42 C43: library part CAPC00002, "CAP,X5R,0.1uF,10%,6.3V, 0402,#", Dielectric=X5R, Manufacturer=TDK, Manufacturer 2=Murata, Manufacturer Part Number=C1005X5R0J104K, Manufacturer Part Number 2=GRM155R60J104KA01D, Package=0402, Supplier Part Number 1=445-1266-1-ND, Tolerance=10%, Voltage=6.3V
C2 C4 C12 C15: library part CAPC00005, "CAP,X5R,1.0uF,10%,6.3V, 0402,#", Dielectric=X5R, Manufacturer=Murata, Manufacturer 2=Samsung, Manufacturer Part Number=GRM155R60J105KE19D, Manufacturer Part Number 2=CL05A105KQ5NNNC, Package=0402, Supplier Part Number 1=490-1320-1-ND, Tolerance=10%, Voltage=6.3V
C3 C9 C47 C49 C50 C52 C55: library part CAPC00073, "CAP,X5R,0.1uF,20%,6.3V,0201", Dielectric=X5R, Manufacturer=TDK, Manufacturer 2=Samsung, Manufacturer Part Number=C0603X5R0J104M030BC, Manufacturer Part Number 2=CL03A104MQ3NNNC, Package=0201, Supplier Part Number 1=445-4711-1-ND, Tolerance=20%, Voltage=6.3V
C10 C11: library part CAPC00146, "CAP,C0G,8pF,±0.5pF,50V,0201", Dielectric=C0G, Manufacturer=Yageo, Manufacturer Part Number=CC0201DRNPO9BN8R0, Package=0201, Supplier Part Number 1=311-3679-1-ND, Tolerance=0.5pF, Voltage=50V
C13 C29: library part CAPC00040, "CAP,X5R,2.2uF,10%,6.3V,0402#", Dielectric=X5R, Manufacturer=TDK, Manufacturer Part Number=C1005X5R0J225K, Package=0402, Supplier Part Number 1=445-6847-1-ND, Tolerance=10%, Voltage=6.3V
C23 C48: library part CAPC00078, "CAP,C0G,33pF,5%,25V,0201", Dielectric=C0G, Manufacturer=Murata, Manufacturer 2=TDK, Manufacturer Part Number=GRM0335C1E330JD01D, Manufacturer Part Number 2=C0603C0G1E330J030BA, Package=0201, Supplier Part Number 1=490-1255-1-ND, Tolerance=5%, Voltage=25V
C24 C51: library part CAPC00143, "CAP,C0G,10pF,5%,50V,0201", Dielectric=C0G, Manufacturer=Murata, Manufacturer Part Number=GRM0335C1H100JA01D, Package=0201, Supplier Part Number 1=490-6112-1-ND, Tolerance=5%, Voltage=50V
C25 C45 C46: library part CAPC00061, "CAP,C0G,100pF,5%,25V,0402", Dielectric=C0G, Manufacturer=TDK, Manufacturer Part Number=C1005C0G1E101J, Package=0402, Supplier Part Number 1=445-6845-1-ND, Tolerance=5%, Voltage=25V
C44: library part CAPC00012, "CAP,X5R,4.7uF,20%,6.3V, 0402,#", Dielectric=X5R, Manufacturer=Murata, Manufacturer 2=Samsung, Manufacturer Part Number=GRM155R60J475ME47D, Manufacturer Part Number 2=CL05A475MQ5NQNC, Package=0402, Supplier Part Number 1=490-5915-1-ND, Tolerance=20%, Voltage=6.3V
C56 C57 C68 C69: library part CAPC00130, "CAP,X5R,47uF,20%,10V,0805", Dielectric=X5R, Manufacturer=Murata, Manufacturer Part Number=GRM21BR61A476ME15L, Package=0805, Supplier Part Number 1=490-9961-1-ND, Tolerance=20%, Voltage=10V
C65 C66: library part CAPC00072, "CAP,C0G,12pF,5%,25V,0201", Dielectric=C0G, Manufacturer=Murata, Manufacturer 2=TDK, Manufacturer Part Number=GRM0335C1E120JA01D, Manufacturer Part Number 2=C0603C0G1E120J030BA, Package=0201, Supplier Part Number 1=490-3144-1-ND, Tolerance=5%, Voltage=25V
D1: library part LED00056, "LED, Green, 2.8V, 527nm, 5mA, 0603", Color=Green, Current - Test=5mA, Manufacturer=Liteon, Manufacturer Part Number=LTST-C193TGKT-5A, Millicandela Rating (min)=154mcd, Package=0603, Supplier Part Number 1=160-1832-1-ND, Voltage - Forward (Vf) Typ=2.8V
E1: library part CON00098, "Edge Connector, NGFF Key E"
F1 F2: library part ELEC00015
FB1: library part FB00010, "FERR BD, 120 Ohm @ 100Mhz, 1.3 A, 90 mOhm, 0402", Current Rating=1.3A, DC Resistance (DCR)="90 mOhm", Impedance @ Frequency="120 Ohms @ 100MHz", Manufacturer=Murata, Manufacturer Part Number=BLM15PD121SN1D, Package=0402, Supplier Part Number 1=490-5203-1-ND
J1 J2: library part CON00013, "Conn, Coax, U.FL, non-switch, Rcpt, 2.6 x 2.5mm, SMD", Manufacturer=Hirose, Manufacturer Part Number=U.FL-R-SMT(01), Supplier Part Number 1=H9161CT-ND
L5: library part IND00041, "IND, 27nH, 5%, 700 mOhm, 0402, 300mA", Current=300mA, Current - Saturation=-, DC Resistance (DCR)="700 mOhm (Max)", Manufacturer="Taiyo Yuden", Manufacturer Part Number=HK100527NJ-T, Package=0402, Supplier Part Number 1=587-1524-1-ND, Tolerance=5%
MOV1: library part TVS00012, "Varistor,15V,0.05pF,0402", Manufacturer=Murata, Manufacturer Part Number=LXES15AAA1-133, Supplier Part Number 1=490-13209-1-ND, Varistor Voltage=40VAC
Q1 Q2: library part NFET00011, "NFET, 20V, 1.A, SOT323", Current - Continuous Drain (Id) @ 25° C=1A, Drain to Source Voltage (Vdss)=20V, Manufacturer="Diodes Incorporated", Manufacturer Part Number=DMG1012UW-7, Package=SOT323, Power - Max=290mW, Supplier Part Number 1=DMG1012UW-7DICT-ND
Q3: library part NFET00007, "NFET+PFET, 20V, 740mA, SOT563", Current - Continuous Drain (Id) @ 25° C=740mA, Drain to Source Voltage (Vdss)=20V, Manufacturer="Diodes Incorporated", Package=SOT563, Power - Max=450mW, Supplier Part Number 1=DMC2400UV-7DICT-ND
Q4: library part NFET00007, "NFET+PFET, 20V, 740mA, SOT563", Current - Continuous Drain (Id) @ 25° C=740mA, Drain to Source Voltage (Vdss)=20V, Manufacturer="Diodes Incorporated", Manufacturer Part Number=DMC2400UV-7, Package=SOT563, Power - Max=450mW, Supplier Part Number 1=DMC2400UV-7DICT-ND
R1 R3 R4 R8: library part RES00074, "RES,10K Ohm,1%,0.05W,0201", Manufacturer=Panasonic, Manufacturer Part Number=ERJ-1GEF1002C, Package=0201, Power=0.05W, Supplier Part Number 1=P10.0KABCT-ND, Tolerance=1%
R2: library part RES00019, "RES,0 Ohm,0.063W,0402", Manufacturer=Yageo, Manufacturer 2=ROHM, Manufacturer Part Number=RC0402JR-070RL, Manufacturer Part Number 2=MCR01MRTJ000, Package=0402, Power=0.063W, Supplier Part Number 1=311-0.0JRCT-ND, Tolerance=0%
R5 R6 R9 R10 R11 R25 R28 R29 R42: library part RES00067, "RES,100K,1%,0.05W,0201", Manufacturer="Vishay Dale", Manufacturer Part Number=CRCW0201100KFNED, Package=0201, Power=0.05W, Supplier Part Number 1=541-100KABCT-ND, Tolerance=1%
R7: library part RES00011, "RES,220 Ohm,5%,0.063W,0402", Manufacturer=Yageo, Manufacturer 2=Panasonic, Manufacturer Part Number=RC0402JR-07220RL, Manufacturer Part Number 2=ERJ-2GEJ221X, Package=0402, Power=0.063W, Supplier Part Number 1=311-220JRCT-ND, Tolerance=5%
R21: library part RES00071, "RES,10 Ohm,1% 0.1W,0402", Manufacturer=Panasonic, Manufacturer Part Number=ERJ-2RKF10R0X, Package=0402, Power=0.1W, Supplier Part Number 1=P10.0LCT-ND, Tolerance=1%
R30 R41: library part RES00066, "RES,1M,1%,0.05W,0201", Manufacturer=Rohm, Manufacturer 2=Samsung, Manufacturer Part Number=MCR006YRTF1004, Manufacturer Part Number 2=RC0603F105CS, Package=0201, Power=0.05W, Supplier Part Number 1=RHM1.0MCBCT-ND, Tolerance=1%
U8: library part IC00202, "IC, SPI Flash, 64Mbit, 104MHz, QSPI, 2.7V-3.6V, SOIC-8W", Manufacturer=Spansion, Manufacturer Part Number=S25FL064LABMFI013, Supplier Part Number 1=428-4073-1-ND
U9: library part IC00267, "IC, Logic, 8-bit Level Translator, auto-direction, 20VQFN", Manufacturer=TI, Supplier Part Number 1=296-24806-1-ND
U10: library part IC00236, "IC, eSIM, SLM 76CF3201P, 320kB Flash, 8kB RAM, 8WSON", Manufacturer=Infineon, Manufacturer Part Number="SLM 76CF3201P"
U11: library part MOD00039, "Module, Quectel BG96, LTE Cat M1 + GNSS", Manufacturer=Quectel, Manufacturer Part Number=BG96MA-128-SNN
U17: library part MOD00041, "IC, STM32F413ZHJ, preprogrammed impOS, 1.5MB Flash, 100Mhz", Manufacturer="ST Micro", Manufacturer Part Number=STM32F413ZHJ, Manufacturer_Part_Number=stm32f4xxj1, Supplier Part Number 1=497-17016-ND
W1: library part ELEC00024, "Throughhole Shortpads"
Y1: library part XTAL00031, "XTAL, 32.768kHz, 20ppm, 6pF, 90K Ohm, 2012", Frequency=32.768kHz, Frequency Stability=-, Frequency Tolerance=20ppm, Load Capacitance=7pF, Manufacturer=ECS, Manufacturer Part Number=ECS-.327-6-12-TR, Operating Mode=Fundamental, Package=2-SMD, Supplier Part Number 1=XC1945CT-ND
Y2: library part XTAL00024, "XTAL, 26MHz, 20ppm, 8pF, 100 Ohm, 2016", Frequency=26MHz, Frequency Stability=20ppm, Frequency Tolerance=15ppm, Load Capacitance=8pF, Manufacturer=NDK, Manufacturer Part Number=NX2016SA-26MHZ-EXS00A-CS06025, Operating Mode=Fundamental, Package=XTAL_20X15X07-4N, Supplier Part Number 1=644-1213-1-ND

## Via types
v1: diameter 12, hole 6, Top Layer to Bottom Layer, tented both sides, 300 vias
v2: diameter 16, hole 8, Top Layer to Bottom Layer, tented both sides, 95 vias
v3: diameter 12, hole 6, Top Layer to Signal Layer 1, tented both sides, 86 vias
v4: diameter 141.73, hole 137.8, Top Layer to Bottom Layer, tented both sides, 1 vias

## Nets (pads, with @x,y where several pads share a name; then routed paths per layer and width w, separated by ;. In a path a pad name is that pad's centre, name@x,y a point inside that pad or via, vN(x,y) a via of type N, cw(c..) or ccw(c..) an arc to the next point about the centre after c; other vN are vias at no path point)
BOOT0: R1.1 U17.D5 | length 384.4
  Top Layer w4: R1.1@-295,-975.98 -295,-976.97 -290.11,-981.86 -289.13,-981.86 -283.85,-987.13 -283.85,-987.66 v1(-283.34,-988.17) ; U17.D5@-77.28,-823.7 -62.24,-808.66 v1(-59.79,-808.66)
  Bottom Layer w4: v1(-283.34,-988.17) -281.81,-986.64 -277.2,-986.64 -263.46,-972.9 -215.44,-972.9 ; -215.43,-972.9 -146.89,-972.9 -85.45,-911.45 -85.45,-834.32 v1(-59.79,-808.66)
BOOT1: R8.1 U17.J5 | length 473.9
  Top Layer w4: R8.1@-265,-975.98 -265,-976.97 -260.11,-981.86 -258.56,-981.86 -256.01,-984.4 v1(-250,-984.4) ; U17.J5@80.2,-823.7 80.2,-825.63 94,-839.44 v1(94,-841.37)
  Bottom Layer w4: v1(-250,-984.4) -147.79,-984.4 -77.95,-914.56 -77.95,-866.35 -64.51,-852.92 82.45,-852.92 v1(94,-841.37)
CELL_PWR_EN: R41.2 U9.10 U17.D7 | length 816.3
  Top Layer w4: U9.10@-201.14,-1184.93 -211.35,-1184.93 -214.86,-1181.42 -214.86,-1174.13 -205.8,-1165.06 -205.8,-1152.94 -226.93,-1131.81 -260.19,-1131.81 -340,-1052 -340,-926.91 -329.21,-916.12 -317.2,-916.12 -311.39,-910.31 -303.57,-910.31 -277.04,-883.78 -277.04,-809.04 -280.88,-805.2 -280.88,-741.86 R41.2@-280,-740.98 -269.95,-740.98 -253,-757.93 -253,-777.26 -245.07,-785.18 -206.13,-785.18 v3(-199,-778.06) ; v3(-124.78,-777.46) -124.48,-777.15 -106.31,-777.15 -89.87,-760.71 U17.D7@-77.28,-760.71
  Signal Layer 1 w4: v3@-199,-777.46 v3(-124.78,-777.46)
